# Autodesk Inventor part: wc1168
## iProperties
Shininess: 64.0
Length Units: 11272
Angle Units: 11279
Time Units: 11290
Mass Units: 11286
Length Display Precision: 3
Angle Display Precision: 2
Compacted: True
Part Number: wc1168
Document SubType Name: Modeling
Created: 2004-08
Designer: John Blackburn
Manufacturer: Standard
Standards Organization: Custom
Material: Phenolic
Density: 0.0
Volumn: 0.0
Area: 0.0
PropertySet Name: Model Information
Control State: 0
Master: False
Checked Out: False
Author: John Blackburn
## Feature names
1. Base1
